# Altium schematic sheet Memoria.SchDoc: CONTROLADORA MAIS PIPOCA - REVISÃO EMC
size A3; DocumentNumber: GA0050; SheetNumber: 15; SheetTotal: 17
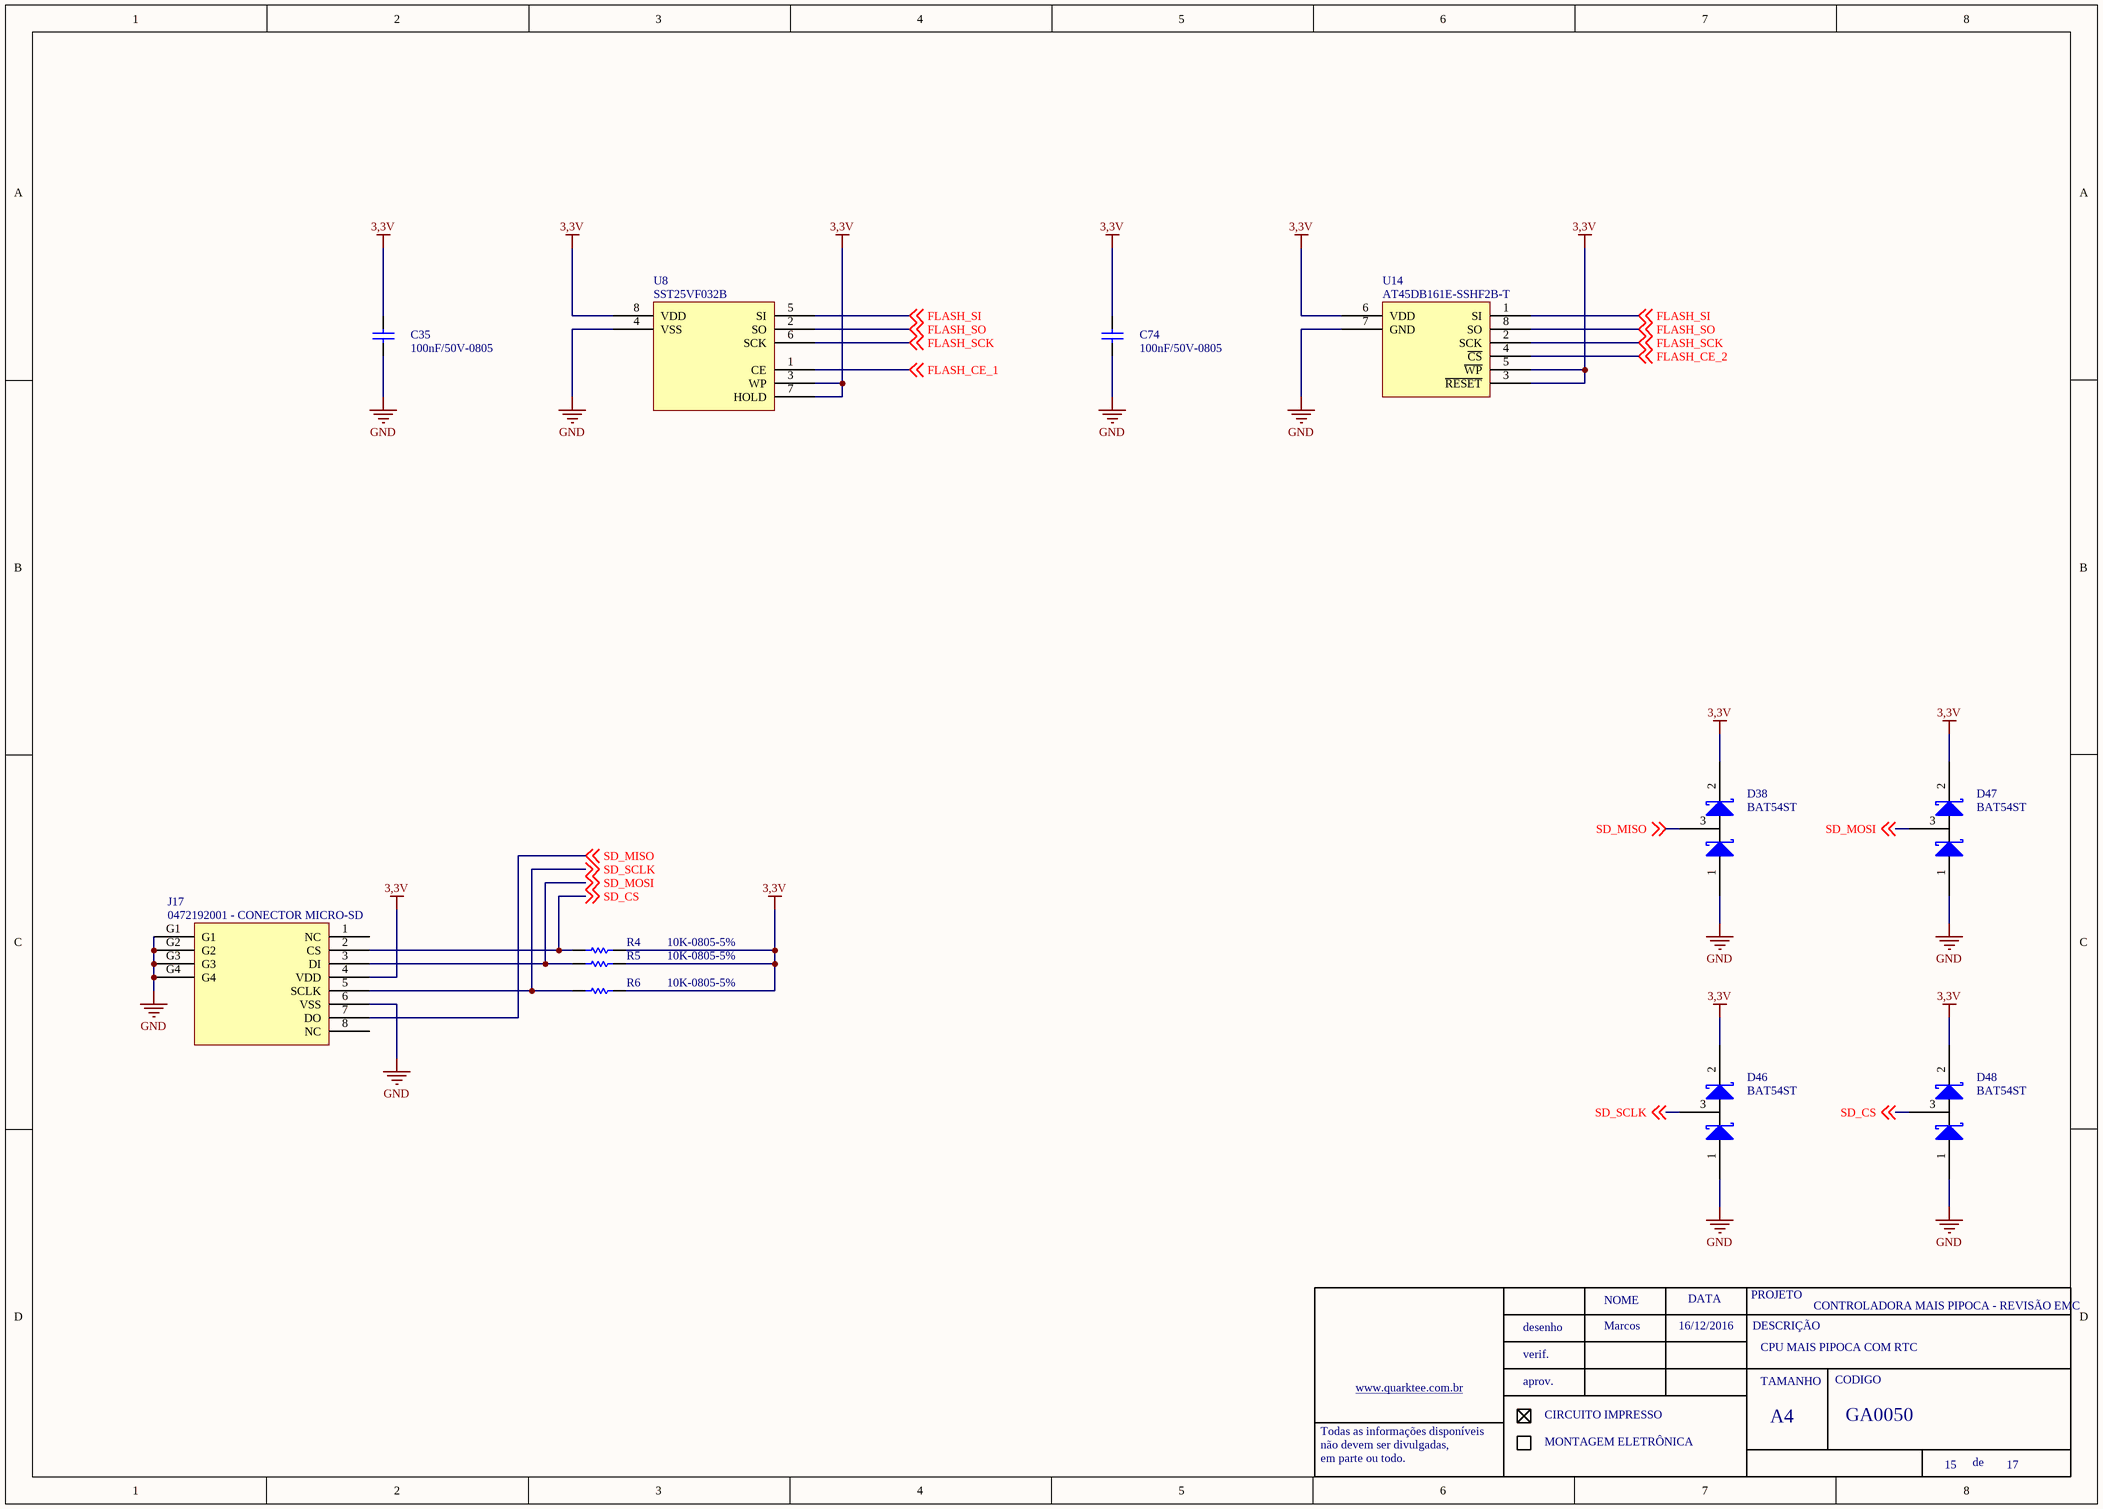
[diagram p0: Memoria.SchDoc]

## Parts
C35  100nF/50V-0805  [0805-REVISADO ONDA]
C74  100nF/50V-0805  [0805-REVISADO ONDA]
D38  BAT54ST  [SOT23 - REVISADO ONDA]
D46  BAT54ST  [SOT23 - REVISADO ONDA]
D47  BAT54ST  [SOT23 - REVISADO ONDA]
D48  BAT54ST  [SOT23 - REVISADO ONDA]
J17  0472192001 - CONECTOR MICRO-SD
R4  10K-0805-5%  [0805-REVISADO ONDA]
R5  10K-0805-5%  [0805-REVISADO ONDA]
R6  10K-0805-5%  [0805-REVISADO ONDA]
U8  SST25VF032B  [SOIC LARGO ATMEL]
U14  AT45DB161E-SSHF2B-T

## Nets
3,3V: C35.2 C74.2 D38.2 D46.2 D47.2 D48.2 J17.4(VDD) R4.1 R5.1 R6.1 U8.3(WP) U8.7(HOLD) U8.8(VDD) U14.3(~{RESET}) U14.5(~{WP}) U14.6(VDD)
GND: C35.1 C74.1 D38.1 D46.1 D47.1 D48.1 J17.6(VSS) J17.G1 J17.G2 J17.G3 J17.G4 U8.4(VSS) U14.7(GND)
FLASH_CE_1: U8.1(CE) ; off-sheet FLASH_CE_1
FLASH_CE_2: U14.4(~{CS}) ; off-sheet FLASH_CE_2
FLASH_SCK: U8.6(SCK) U14.2(SCK) ; off-sheet FLASH_SCK
FLASH_SI: U8.5(SI) U14.1(SI) ; off-sheet FLASH_SI
FLASH_SO: U8.2(SO) U14.8(SO) ; off-sheet FLASH_SO
SD_CS: D48.3 J17.2(CS) R4.2 ; off-sheet SD_CS
SD_MISO: D38.3 J17.7(DO) ; off-sheet SD_MISO
SD_MOSI: D47.3 J17.3(DI) R5.2 ; off-sheet SD_MOSI
SD_SCLK: D46.3 J17.5(SCLK) R6.2 ; off-sheet SD_SCLK

Not connected (* = marked no-connect by the designer): J17 1(NC) 8(NC)

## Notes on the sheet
- Marcos
- 16/12/2016
- CPU MAIS PIPOCA COM RTC

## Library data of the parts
C35 C74 = 100nF/50-0805-NPO
J17 = CONECTOR MICRO-SD
U8 = SST25VF032B: ERP: FALTA CADASTRAR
